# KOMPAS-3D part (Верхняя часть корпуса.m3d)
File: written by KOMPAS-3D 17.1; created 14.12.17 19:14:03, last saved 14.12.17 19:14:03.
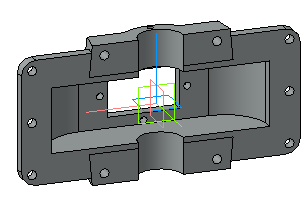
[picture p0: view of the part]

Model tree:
1. Операция без истории:1

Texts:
  Верхняя часть корпуса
